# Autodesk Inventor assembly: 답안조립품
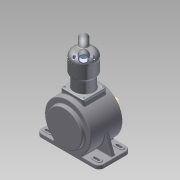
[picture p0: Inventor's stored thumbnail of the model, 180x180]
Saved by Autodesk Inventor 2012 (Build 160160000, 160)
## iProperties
Created: 2015-06
Part Number: 답안조립품
Document SubType Name: Assembly
Designer: Administrator
Author: Administrator
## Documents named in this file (11)
- C:\Documents and Settings\Administrator\바탕 화면\450605v1005\답안조립품.iam
- C:\Documents and Settings\Administrator\바탕 화면\450605v1005\본체.ipt
- C:\Documents and Settings\Administrator\바탕 화면\450605v1005\베어링 6204.ipt
- C:\Documents and Settings\Administrator\바탕 화면\450605v1005\크랭크 서브축.ipt
- C:\Documents and Settings\Administrator\바탕 화면\450605v1005\메인 크랭크 축-구동부.ipt
- C:\Documents and Settings\Administrator\바탕 화면\450605v1005\커넥팅 로드.ipt
- C:\Documents and Settings\Administrator\바탕 화면\450605v1005\실린더.ipt
- C:\Documents and Settings\Administrator\바탕 화면\450605v1005\실린더헤드.ipt
- C:\Documents and Settings\Administrator\바탕 화면\450605v1005\메인커버.ipt
- C:\Documents and Settings\Administrator\바탕 화면\450605v1005\오일실.ipt
- C:\Documents and Settings\Administrator\바탕 화면\450605v1005\M4x0.7.ipt
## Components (4 placed, 1 different names)
1. M4x0.7:1
2. M4x0.7:2
3. M4x0.7:3
4. M4x0.7:4
